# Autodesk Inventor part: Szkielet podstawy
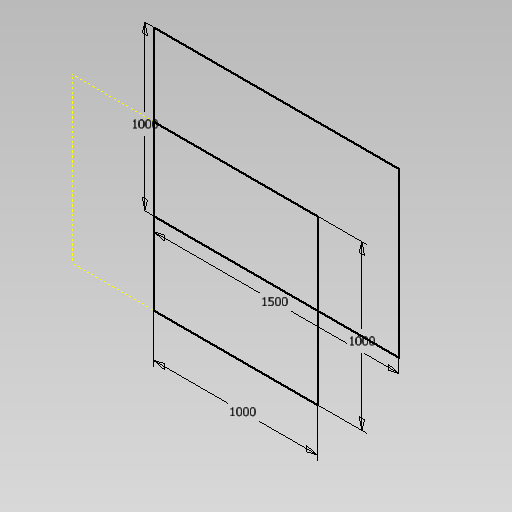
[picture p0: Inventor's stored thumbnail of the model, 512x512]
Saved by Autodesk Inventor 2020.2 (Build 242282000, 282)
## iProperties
Created: 2006-08
Part Number: Szkielet podstawy
Document SubType Name: Modeling
Designer: F.Stasiak
Density: 1 g/cm^3
Material: Ogólny
Appearance: Domyślna
Manager: www.cadconsulting.pl
Company: Fabian Stasiak CAD Consulting
Author: F.Stasiak
Subject: Zbiór ćwiczeń. Autodesk Inventor 2020. Kurs podstawowy
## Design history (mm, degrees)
sketch "Szkic1"
  geometry: L1 (0, 0)-(1500, 0); L2 (1500, 0)-(1500, 1000); L3 (1500, 1000)-(0, 1000); L4 (0, 1000)-(0, 0)
  constraints: 8 end point, 2 parallel, 1 horizontal, 1 perpendicular
  dimensions: "d0" = 1500 distance of L1.start L1.end; "d1" = 1000 distance of L3.end L1.start
node "Płaszczyzna konstrukcyjna1"
sketch "Szkic2"
  geometry: L1 (500, 1000)-(1500, 1000); L2 (1500, 1000)-(1500, 0); L3 (1500, 0)-(500, 0); L4 (500, 0)-(500, 1000); L5 (1500, 1000)-(0, 1000) reference; L6 (0, 1000)-(0, 0) reference; L7 (0, 0)-(1500, 0) reference; L8 (1500, 0)-(1500, 1000) reference
  constraints: 8 end point, 2 collinear, 2 parallel, 1 horizontal, 1 perpendicular
  dimensions: "d3" = 1000 distance of L2.end L3.end; "d4" = 1000 distance of L1.end L2.end
node "Korpusy bryłowe"
node "Korpusy powierzchniowe"
